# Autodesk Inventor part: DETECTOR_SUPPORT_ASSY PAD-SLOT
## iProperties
Shininess: 64.0
Length Units: 11272
Angle Units: 11279
Time Units: 11290
Mass Units: 11286
Length Display Precision: 3
Angle Display Precision: 2
Compacted: True
Part Number: DETECTOR_SUPPORT_ASSY PAD-SLOT
Document SubType Name: Modeling
Created: 2004-08
Designer: John Blackburn
Material: STAINLESS_STEEL, AUSTENITIC
Manufacturer: Standard
Standards Organization: Custom
Density: 0.0
Volumn: 0.0
Area: 0.0
PropertySet Name: Model Information
Control State: 0
Master: False
Checked Out: False
Author: John Blackburn
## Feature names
1. ExtrusionBlind1
2. Hole1
3. Rectangular Pattern1
4. ExtrusionMidplane1
